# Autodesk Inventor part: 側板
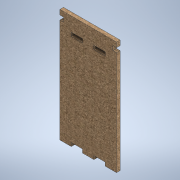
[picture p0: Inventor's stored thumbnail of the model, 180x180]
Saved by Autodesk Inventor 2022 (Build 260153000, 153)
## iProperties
Created: 2024-11
Part Number: 側板
Material: MDF 中密度繊維ボード
Document SubType Name: Modeling
Designer: shimizu
Density: 0.8 g/cm^3
Appearance: ダンボール - 段ボール紙
Author: shimizu
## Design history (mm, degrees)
sketch "スケッチ1"
  geometry: L1 (-20.243, 58.107)-(19.757, 58.107); L2 (-4.243, -21.893)-(-4.243, -19.393); L3 (-4.243, -19.393)-(-12.243, -19.393); L4 (-12.243, -19.393)-(-12.243, -21.893); L5 (11.757, -21.893)-(11.757, -19.393); L6 (11.757, -19.393)-(3.757, -19.393); L7 (3.757, -19.393)-(3.757, -21.893); L8 (-12.243, 48.107)-(-4.243, 48.107); L9 (-4.243, 48.107)-(-4.243, 45.607); L10 (-4.243, 45.607)-(-12.243, 45.607); L11 (-12.243, 45.607)-(-12.243, 48.107); L12 (3.757, 48.107)-(11.757, 48.107); L13 (11.757, 48.107)-(11.757, 45.607); L14 (11.757, 45.607)-(3.757, 45.607); L15 (3.757, 45.607)-(3.757, 48.107); L16 (-12.243, -21.893)-(-20.243, -21.893); L17 (19.757, -21.893)-(11.757, -21.893); L18 (3.757, -21.893)-(-4.243, -21.893); L19 (-20.243, 54.607)-(-17.743, 54.607); L20 (-17.743, 54.607)-(-17.743, 51.607); L21 (-17.743, 51.607)-(-20.243, 51.607); L22 (19.757, 54.607)-(17.257, 54.607); L23 (17.257, 54.607)-(17.257, 51.607); L24 (17.257, 51.607)-(19.757, 51.607); L25 (-20.243, -21.893)-(-20.243, 51.607); L26 (-20.243, 54.607)-(-20.243, 58.107); L27 (19.757, 58.107)-(19.757, 54.607); L28 (19.757, 51.607)-(19.757, -21.893); 1 further point
  constraints: 56 end point, 15 parallel, 6 perpendicular, 5 horizontal
extrude "押し出し1" new body sketch "スケッチ1" distance "d13" = 2.5; taper "d14" = 0 deg
node "ソリッド1"
